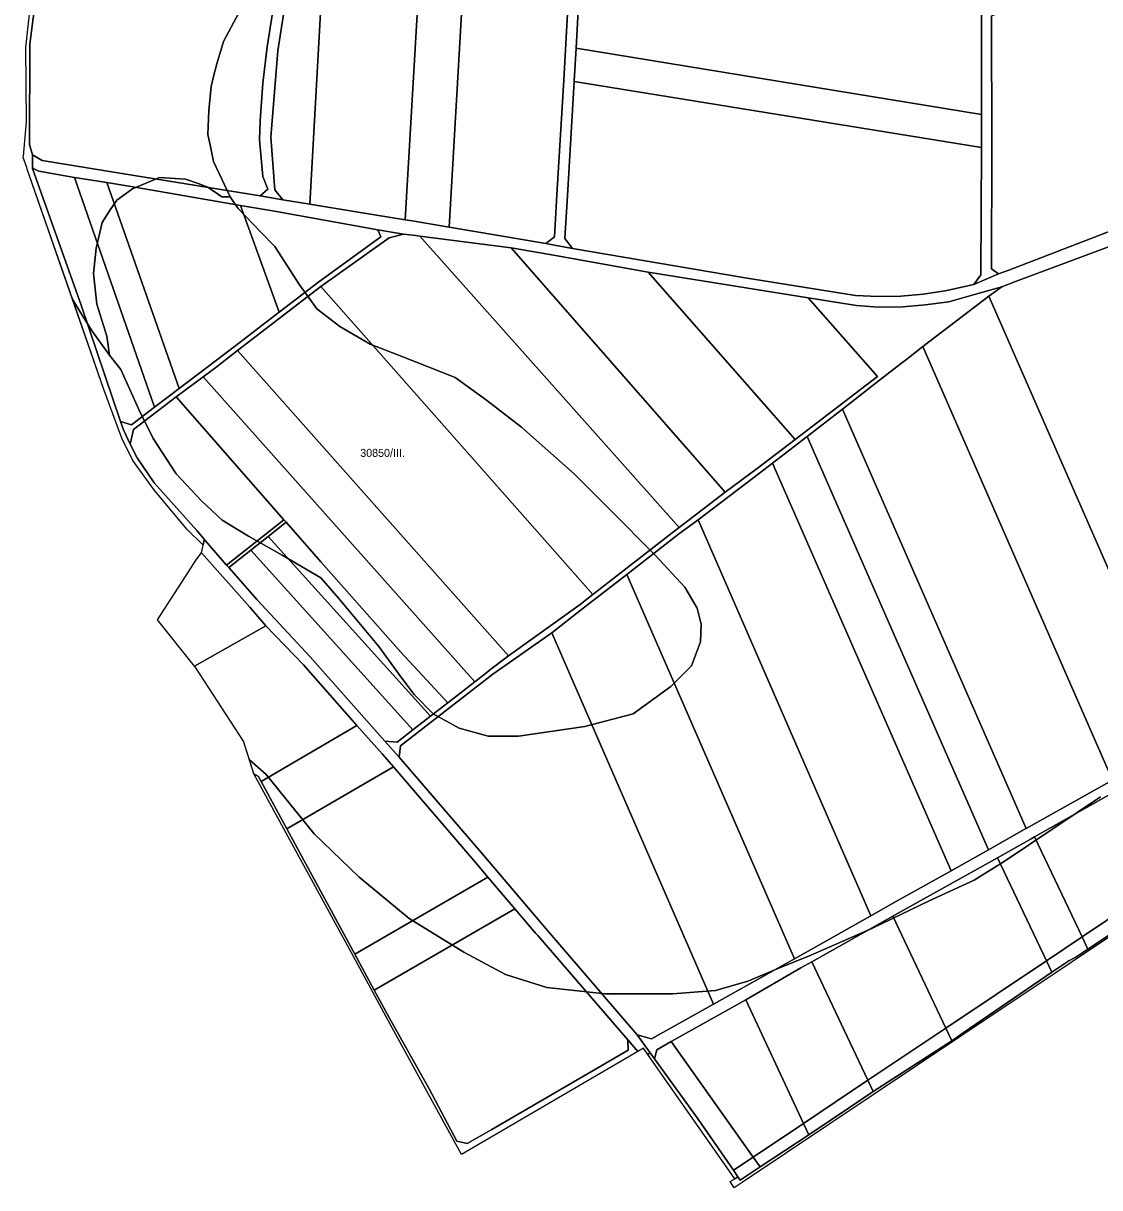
# Model space of a CAD drawing. Extents: x -541351 to -537540, y -1162694 to -1159725.
# Drawn here: x -541335 to -540662, y -1161930 to -1161203 of the extents above; entities that cross this region are included whole.
import ezdxf

# ---------------------------------------------------------------- set-up
doc = ezdxf.new("R2010")
doc.units = 0
for name, color, linetype in [('95560013', 7, 'Continuous'), ('95630013', 7, 'Continuous'), ('95640013', 7, 'Continuous'), ('95660013', 7, 'Continuous')]:
    doc.layers.add(name, color=color, linetype=linetype)

msp = doc.modelspace()

# ---------------------------------------------------------------- linework, layer by layer
at = {"layer": '95560013'}
for points in [[(-541002.5, -1161335.95), (-541008.05, -1161340.22), (-541068.49, -1161330.02), (-541054.64, -1161091.86), (-541038.24, -1161076.76), (-541018.02, -1161051.7), (-541009.77, -1161048.36), (-540991.57, -1161051.36), (-540986.52, -1161057.36), (-540989.14, -1161101.78), (-540991.75, -1161147.06), (-540996.64, -1161238.13), (-541001.01, -1161309.69)], [(-540986.52, -1161057.36), (-540991.57, -1161051.36), (-540975.41, -1161053.82), (-540979.98, -1161058.32), (-540982.72, -1161102.03), (-540985.21, -1161147.42), (-540989.12, -1161218.21), (-540990.18, -1161238.48), (-540990.23, -1161238.98), (-540994.49, -1161310.1), (-540996.06, -1161337.06), (-540991.27, -1161343.31), (-541002.57, -1161341.19), (-541008.05, -1161340.22), (-541002.5, -1161335.95), (-541001.01, -1161309.69), (-540996.64, -1161238.13), (-540991.75, -1161147.06), (-540989.14, -1161101.78)], [(-540741.17, -1161091.8), (-540735.93, -1161097.29), (-540736, -1161144.39), (-540735.68, -1161196.89), (-540735.74, -1161259.49), (-540989.12, -1161218.21), (-540985.21, -1161147.42), (-540982.72, -1161102.03), (-540979.98, -1161058.32), (-540975.41, -1161053.82), (-540941.46, -1161059.38), (-540869, -1161071.68), (-540796.53, -1161083.37)], [(-541091.62, -1161326.12), (-541095.8, -1161325.34), (-541083.35, -1161111.3), (-541073.3, -1161109.03), (-541054.64, -1161091.86), (-541068.49, -1161330.02)], [(-541145.22, -1161132.35), (-541126.35, -1161121.54), (-541083.35, -1161111.3), (-541095.8, -1161325.34), (-541125.26, -1161320.58), (-541155.46, -1161315.61)], [(-540725.06, -1161359.22), (-540729.41, -1161355.94), (-540729.28, -1161280.63), (-540729.47, -1161197.86), (-540518.17, -1161114.81), (-540508.04, -1161201.67), (-540500.7, -1161266.6), (-540504.91, -1161273.51), (-540630.42, -1161322.96), (-540718.49, -1161356.81)], [(-541170.97, -1161190.37), (-541166.19, -1161152.97), (-541161.55, -1161143.55), (-541145.22, -1161132.35), (-541155.46, -1161315.61), (-541172.43, -1161312.81), (-541177.3, -1161306.69), (-541179.83, -1161273.84), (-541175.46, -1161219.82)], [(-540990.23, -1161238.98), (-540990.18, -1161238.48), (-540989.12, -1161218.21), (-540735.74, -1161259.49), (-540735.57, -1161280.29)], [(-540800.31, -1161373.2), (-540814.5, -1161372.57), (-540883.34, -1161361.65), (-540991.27, -1161343.31), (-540996.06, -1161337.06), (-540994.49, -1161310.1), (-540990.23, -1161238.98), (-540735.57, -1161280.29), (-540735.58, -1161280.69), (-540736.07, -1161359.79), (-540740.36, -1161365.79), (-540758.33, -1161369.77), (-540772.08, -1161371.79), (-540786.11, -1161373.14)], [(-541273.81, -1161451.48), (-541298.37, -1161378.61), (-541328.81, -1161293.37), (-541328.94, -1161293), (-541328, -1161293.47), (-541324.9, -1161295), (-541302.51, -1161298.95), (-541252.67, -1161442.38), (-541267.05, -1161453.46)], [(-541252.67, -1161442.38), (-541302.51, -1161298.95), (-541282.32, -1161302.16), (-541237.22, -1161430.82)], [(-541264.86, -1161305.04), (-541198.78, -1161316.41), (-541174.69, -1161383.11), (-541202.56, -1161404.53), (-541237.22, -1161430.82), (-541282.32, -1161302.16)], [(-541198.78, -1161316.41), (-541177.67, -1161319.97), (-541113.06, -1161331.61), (-541111.07, -1161335.97), (-541149.92, -1161364.06), (-541174.69, -1161383.11)], [(-540626.04, -1161331.01), (-540602.06, -1161321.76), (-540487.95, -1161583.73), (-540514.53, -1161597.21), (-540593.57, -1161641.71), (-540609.41, -1161650.66), (-540731.05, -1161373.08), (-540722.92, -1161367.3), (-540714.45, -1161363.95)], [(-541237.22, -1161430.82), (-541202.56, -1161404.53), (-541174.69, -1161383.11), (-541149.92, -1161364.06), (-541111.07, -1161335.97), (-541113.06, -1161331.61), (-541096.97, -1161334.3), (-541105.92, -1161336.62), (-541148.7, -1161366.98), (-541200.73, -1161407.02), (-541214.31, -1161417.57), (-541222.15, -1161423.45), (-541239.06, -1161436.07), (-541265.8, -1161456.42), (-541267.7, -1161465.57), (-541271.92, -1161456.53), (-541273.81, -1161451.48), (-541267.05, -1161453.46), (-541252.67, -1161442.38)], [(-541096.97, -1161334.3), (-541090.82, -1161335.06), (-541086.82, -1161335.7), (-540924.65, -1161517.59), (-540927.06, -1161519.46), (-540978.65, -1161559.41), (-541148.7, -1161366.98), (-541105.92, -1161336.62)], [(-541086.82, -1161335.7), (-541029.57, -1161342.88), (-540895.88, -1161495.62), (-540924.65, -1161517.59)], [(-540895.88, -1161495.62), (-541029.57, -1161342.88), (-541001.92, -1161347.64), (-540944.09, -1161357.99), (-540852.18, -1161462.55), (-540875.88, -1161480.69)], [(-540944.09, -1161357.99), (-540883.03, -1161367.85), (-540843.94, -1161374.18), (-540800.7, -1161423.2), (-540852.18, -1161462.55)], [(-541148.7, -1161366.98), (-540978.65, -1161559.41), (-540986.54, -1161565.79), (-541031.23, -1161597.84), (-541200.73, -1161407.02)], [(-540852.18, -1161462.55), (-540800.7, -1161423.2), (-540843.94, -1161374.18), (-540813.72, -1161378.95), (-540800.34, -1161380.02), (-540784.84, -1161379.79), (-540770.8, -1161378.57), (-540756.03, -1161376.56), (-540740.09, -1161372.1), (-540722.92, -1161367.3), (-540731.05, -1161373.08), (-540772.43, -1161404.49), (-540782.43, -1161412.5), (-540785.62, -1161415.04), (-540799.44, -1161425.52), (-540822.56, -1161443.77), (-540844.61, -1161460.72), (-540866.29, -1161477.37), (-540874.33, -1161483.65), (-540912.8, -1161512.76), (-540925.13, -1161521.9), (-540957.39, -1161546.93), (-540985.59, -1161568.9), (-541004.21, -1161583.4), (-541041.07, -1161609.24), (-541098.89, -1161653.97), (-541099.72, -1161661.19), (-541108.6, -1161651.17), (-541100.92, -1161651.74), (-541091.05, -1161644.07), (-541080.04, -1161635.58), (-541069.2, -1161627.21), (-541052.46, -1161614.04), (-541044.94, -1161608.22), (-541043.12, -1161606.82), (-541031.23, -1161597.84), (-540986.54, -1161565.79), (-540978.65, -1161559.41), (-540927.06, -1161519.46), (-540924.65, -1161517.59), (-540895.88, -1161495.62), (-540875.88, -1161480.69)], [(-540772.43, -1161404.49), (-540731.05, -1161373.08), (-540609.41, -1161650.66), (-540636.75, -1161665.9), (-540653.69, -1161675.45)], [(-540799.44, -1161425.52), (-540785.62, -1161415.04), (-540782.43, -1161412.5), (-540772.43, -1161404.49), (-540653.69, -1161675.45), (-540664.54, -1161681.55), (-540667.99, -1161683.49), (-540707.7, -1161705.8), (-540822.56, -1161443.77)], [(-541214.31, -1161417.57), (-541200.73, -1161407.02), (-541031.23, -1161597.84), (-541043.12, -1161606.82), (-541044.94, -1161608.22), (-541052.46, -1161614.04), (-541222.15, -1161423.45)], [(-541171.76, -1161512.77), (-541239.06, -1161436.07), (-541222.15, -1161423.45), (-541052.46, -1161614.04), (-541069.2, -1161627.21), (-541098.59, -1161595.53), (-541148.61, -1161539.06), (-541170.36, -1161514.21)], [(-541267.7, -1161465.57), (-541265.8, -1161456.42), (-541239.06, -1161436.07), (-541171.76, -1161512.77), (-541207.48, -1161541.15), (-541220.9, -1161525.72), (-541221.52, -1161524.98), (-541226.07, -1161519.49), (-541252.77, -1161489.7), (-541263.44, -1161474.03)], [(-540844.61, -1161460.72), (-540822.56, -1161443.77), (-540707.7, -1161705.8), (-540708.95, -1161706.43), (-540731.37, -1161719.05)], [(-540866.29, -1161477.37), (-540844.61, -1161460.72), (-540731.37, -1161719.05), (-540754.61, -1161732.14)], [(-540874.33, -1161483.65), (-540866.29, -1161477.37), (-540754.61, -1161732.14), (-540788.4, -1161751), (-540804.81, -1161760.28), (-540912.8, -1161512.76)], [(-541207.48, -1161541.15), (-541171.76, -1161512.77), (-541170.36, -1161514.21), (-541181.49, -1161523.17), (-541192.32, -1161531.89), (-541206.21, -1161542.7)], [(-540804.81, -1161760.28), (-540852.63, -1161787.05), (-540957.39, -1161546.93), (-540925.13, -1161521.9), (-540912.8, -1161512.76)], [(-541181.49, -1161523.17), (-541170.36, -1161514.21), (-541148.61, -1161539.06), (-541098.59, -1161595.53), (-541069.2, -1161627.21), (-541080.04, -1161635.58)], [(-541181.49, -1161523.17), (-541080.04, -1161635.58), (-541091.05, -1161644.07), (-541192.32, -1161531.89)], [(-541182.97, -1161579.01), (-541227.53, -1161604.31), (-541250.72, -1161575.22), (-541242.35, -1161562.34), (-541233.17, -1161548.21), (-541226.45, -1161537.87), (-541223.3, -1161533.47), (-541193.07, -1161567.51)], [(-541188.37, -1161562.9), (-541206.21, -1161542.7), (-541192.32, -1161531.89), (-541091.05, -1161644.07), (-541100.92, -1161651.74), (-541108.6, -1161651.17), (-541155.28, -1161598.47)], [(-540903.21, -1161815.53), (-541004.21, -1161583.4), (-540985.59, -1161568.9), (-540957.39, -1161546.93), (-540852.63, -1161787.05)], [(-541190.56, -1161671.49), (-541196.86, -1161651.1), (-541226.83, -1161605.4), (-541227.53, -1161604.31), (-541182.97, -1161579.01), (-541159.44, -1161603.37), (-541126.02, -1161641.36), (-541185.97, -1161676.37), (-541187.56, -1161673.25)], [(-540903.21, -1161815.53), (-540942, -1161837.03), (-540950.97, -1161834.57), (-541008.22, -1161768), (-541047.04, -1161722.32), (-541099.72, -1161661.19), (-541098.89, -1161653.97), (-541041.07, -1161609.24), (-541004.21, -1161583.4)], [(-541110.06, -1161659.28), (-541103.29, -1161667.11), (-541169.79, -1161705.93), (-541185.97, -1161676.37), (-541126.02, -1161641.36)], [(-540950.54, -1161845.03), (-541060.78, -1161909.35), (-541106.46, -1161825.63), (-541127.01, -1161787.97), (-541190.56, -1161671.49), (-541187.56, -1161673.25), (-541185.97, -1161676.37), (-541169.79, -1161705.93), (-541146.1, -1161749.73), (-541127.42, -1161784.2), (-541115.29, -1161806.63), (-541105.77, -1161824.11), (-541080.97, -1161868.44), (-541063.54, -1161901.08), (-541057.18, -1161902.55), (-541041.8, -1161893.69), (-540956.53, -1161844.18), (-540956.77, -1161837.79)], [(-541103.29, -1161667.11), (-541051.69, -1161727.07), (-541044.31, -1161736.08), (-541127.42, -1161784.2), (-541146.1, -1161749.73), (-541169.79, -1161705.93)], [(-540672.85, -1161773.42), (-540702.46, -1161710.97), (-540654.37, -1161683.86), (-540626.51, -1161742.4)], [(-540672.85, -1161773.42), (-540695.09, -1161788.31), (-540725.63, -1161723.93), (-540704.67, -1161712.23), (-540702.46, -1161710.97)], [(-540725.63, -1161723.93), (-540695.09, -1161788.31), (-540758.04, -1161830.46), (-540791.07, -1161760.57), (-540784.37, -1161756.77)], [(-541127.42, -1161784.2), (-541044.31, -1161736.08), (-541027.44, -1161755.93), (-541115.29, -1161806.63)], [(-541063.54, -1161901.08), (-541080.97, -1161868.44), (-541105.77, -1161824.11), (-541115.29, -1161806.63), (-541027.44, -1161755.93), (-541014.23, -1161771.21), (-541012.92, -1161772.52), (-540956.77, -1161837.79), (-540956.53, -1161844.18), (-541041.8, -1161893.69), (-541057.18, -1161902.55)], [(-540758.04, -1161830.46), (-540806.69, -1161863.04), (-540841.71, -1161789.05), (-540791.07, -1161760.57)], [(-540806.69, -1161863.04), (-540846.94, -1161889.99), (-540882.97, -1161812.68), (-540848.61, -1161792.79), (-540841.71, -1161789.05)], [(-540882.97, -1161812.68), (-540846.94, -1161889.99), (-540878.37, -1161911.03), (-540929.56, -1161838.82)], [(-540929.56, -1161838.82), (-540878.37, -1161911.03), (-540890.7, -1161919.28), (-540912.77, -1161887.31), (-540940.03, -1161849.7), (-540938.7, -1161843.95)]]:
    msp.add_lwpolyline(points, close=True, dxfattribs=at)
for points in [[(-541177.48, -1161188.33), (-541182.21, -1161217.36), (-541184.87, -1161240.05), (-541186.47, -1161263.45), (-541186.85, -1161275.44), (-541184.81, -1161298.35), (-541181.75, -1161306.33), (-541186.56, -1161310.32), (-541265.26, -1161297.71), (-541322.8, -1161288.33), (-541328.76, -1161284.74), (-541330.62, -1161278.35), (-541330.42, -1161215.55), (-541323.15, -1161158.46)], [(-540654.37, -1161683.86), (-540702.46, -1161710.97), (-540704.67, -1161712.23), (-540725.63, -1161723.93), (-540784.37, -1161756.77), (-540791.07, -1161760.57), (-540841.71, -1161789.05), (-540848.61, -1161792.79), (-540882.97, -1161812.68), (-540929.56, -1161838.82), (-540938.7, -1161843.95), (-540940.03, -1161849.7), (-540942.78, -1161845.9), (-540950.97, -1161834.57), (-540942, -1161837.03), (-540903.21, -1161815.53), (-540852.63, -1161787.05), (-540804.81, -1161760.28), (-540788.4, -1161751), (-540754.61, -1161732.14), (-540731.37, -1161719.05), (-540708.95, -1161706.43), (-540707.7, -1161705.8), (-540667.99, -1161683.49), (-540664.54, -1161681.55), (-540653.69, -1161675.45)]]:
    msp.add_lwpolyline(points, dxfattribs=at)
at = {"layer": '95630013'}
msp.add_lwpolyline([(-540610.73, -1161743.43), (-540748.01, -1161835.11), (-540885.29, -1161926.8), (-540890.31, -1161930.15), (-540892.68, -1161926.19), (-540889.95, -1161924.5), (-540887.95, -1161923.26), (-540886.43, -1161925.45), (-540873.99, -1161917.2), (-540843.64, -1161897.07), (-540818.26, -1161879.98), (-540803.39, -1161870.01), (-540754.28, -1161838.41), (-540747.18, -1161833.38), (-540691.67, -1161795.5), (-540681.1, -1161788.46), (-540676.71, -1161786.07), (-540669.18, -1161781.14), (-540622.77, -1161750.26)], dxfattribs=at)
at = {"layer": '95640013'}
for points in [[(-541323.15, -1161158.46), (-541330.42, -1161215.55), (-541330.62, -1161278.35), (-541328.76, -1161284.74), (-541328.93, -1161292.34), (-541328.94, -1161293), (-541328.81, -1161293.37), (-541298.37, -1161378.61), (-541273.81, -1161451.48), (-541271.92, -1161456.53), (-541267.7, -1161465.57), (-541263.44, -1161474.03), (-541252.77, -1161489.7), (-541226.07, -1161519.49), (-541221.52, -1161524.98), (-541222.15, -1161528.65), (-541232.32, -1161518.63), (-541253.05, -1161493.9), (-541266.12, -1161475.84), (-541273, -1161461.76), (-541284.15, -1161431.35), (-541332.09, -1161293.63), (-541332.42, -1161292.68), (-541334.6, -1161286.42), (-541334.52, -1161285.55), (-541332.64, -1161264.13), (-541333.01, -1161217.8), (-541326.12, -1161154.72)], [(-541170.97, -1161190.37), (-541175.46, -1161219.82), (-541179.83, -1161273.84), (-541177.3, -1161306.69), (-541172.43, -1161312.81), (-541186.56, -1161310.32), (-541181.75, -1161306.33), (-541184.81, -1161298.35), (-541186.85, -1161275.44), (-541186.47, -1161263.45), (-541184.87, -1161240.05), (-541182.21, -1161217.36), (-541177.48, -1161188.33)], [(-540729.47, -1161197.86), (-540729.28, -1161280.63), (-540729.41, -1161355.94), (-540725.06, -1161359.22), (-540740.36, -1161365.79), (-540736.07, -1161359.79), (-540735.58, -1161280.69), (-540735.57, -1161280.29), (-540735.74, -1161259.49), (-540735.68, -1161196.89)], [(-540626.04, -1161331.01), (-540714.45, -1161363.95), (-540722.92, -1161367.3), (-540740.09, -1161372.1), (-540756.03, -1161376.56), (-540770.8, -1161378.57), (-540784.84, -1161379.79), (-540800.34, -1161380.02), (-540813.72, -1161378.95), (-540843.94, -1161374.18), (-540883.03, -1161367.85), (-540944.09, -1161357.99), (-541001.92, -1161347.64), (-541029.57, -1161342.88), (-541086.82, -1161335.7), (-541090.82, -1161335.06), (-541096.97, -1161334.3), (-541113.06, -1161331.61), (-541177.67, -1161319.97), (-541198.78, -1161316.41), (-541264.86, -1161305.04), (-541282.32, -1161302.16), (-541302.51, -1161298.95), (-541324.9, -1161295), (-541328, -1161293.47), (-541328.94, -1161293), (-541328.93, -1161292.34), (-541328.76, -1161284.74), (-541322.8, -1161288.33), (-541265.26, -1161297.71), (-541186.56, -1161310.32), (-541172.43, -1161312.81), (-541155.46, -1161315.61), (-541125.26, -1161320.58), (-541095.8, -1161325.34), (-541091.62, -1161326.12), (-541068.49, -1161330.02), (-541008.05, -1161340.22), (-541002.57, -1161341.19), (-540991.27, -1161343.31), (-540883.34, -1161361.65), (-540814.5, -1161372.57), (-540800.31, -1161373.2), (-540786.11, -1161373.14), (-540772.08, -1161371.79), (-540758.33, -1161369.77), (-540740.36, -1161365.79), (-540725.06, -1161359.22), (-540718.49, -1161356.81), (-540630.42, -1161322.96)]]:
    msp.add_lwpolyline(points, dxfattribs=at)
for points in [[(-541047.04, -1161722.32), (-541008.22, -1161768), (-540950.97, -1161834.57), (-540942.78, -1161845.9), (-540944.19, -1161846.83), (-540946.92, -1161842.92), (-540950.54, -1161845.03), (-540956.77, -1161837.79), (-541012.92, -1161772.52), (-541014.23, -1161771.21), (-541027.44, -1161755.93), (-541044.31, -1161736.08), (-541051.69, -1161727.07), (-541103.29, -1161667.11), (-541110.06, -1161659.28), (-541126.02, -1161641.36), (-541159.44, -1161603.37), (-541182.97, -1161579.01), (-541193.07, -1161567.51), (-541223.3, -1161533.47), (-541222.15, -1161528.65), (-541221.52, -1161524.98), (-541220.9, -1161525.72), (-541207.48, -1161541.15), (-541206.21, -1161542.7), (-541188.37, -1161562.9), (-541155.28, -1161598.47), (-541108.6, -1161651.17), (-541099.72, -1161661.19)], [(-540622.77, -1161750.26), (-540669.18, -1161781.14), (-540672.85, -1161773.42), (-540626.51, -1161742.4)], [(-540672.85, -1161773.42), (-540669.18, -1161781.14), (-540676.71, -1161786.07), (-540681.1, -1161788.46), (-540691.67, -1161795.5), (-540695.09, -1161788.31)], [(-540754.28, -1161838.41), (-540758.04, -1161830.46), (-540695.09, -1161788.31), (-540691.67, -1161795.5), (-540747.18, -1161833.38)], [(-540758.04, -1161830.46), (-540754.28, -1161838.41), (-540803.39, -1161870.01), (-540806.69, -1161863.04)], [(-540940.03, -1161849.7), (-540912.77, -1161887.31), (-540890.7, -1161919.28), (-540887.95, -1161923.26), (-540889.95, -1161924.5), (-540944.19, -1161846.83), (-540942.78, -1161845.9)], [(-540818.26, -1161879.98), (-540843.64, -1161897.07), (-540846.94, -1161889.99), (-540806.69, -1161863.04), (-540803.39, -1161870.01)], [(-540846.94, -1161889.99), (-540843.64, -1161897.07), (-540873.99, -1161917.2), (-540878.37, -1161911.03)], [(-540890.7, -1161919.28), (-540878.37, -1161911.03), (-540873.99, -1161917.2), (-540886.43, -1161925.45), (-540887.95, -1161923.26)]]:
    msp.add_lwpolyline(points, close=True, dxfattribs=at)
at = {"layer": '95660013'}
for points in [[(-541199.87, -1161196), (-541209.37, -1161214), (-541213.62, -1161228), (-541215.6, -1161235.78), (-541217.19, -1161242), (-541218.69, -1161257), (-541219.19, -1161272), (-541217.6, -1161279.56), (-541215.62, -1161289), (-541205.37, -1161311), (-541210.5, -1161311), (-541219.19, -1161305), (-541225.38, -1161302.78), (-541233.12, -1161300), (-541249.5, -1161299), (-541266.37, -1161306), (-541276.19, -1161313), (-541280.27, -1161319.22), (-541285.37, -1161327), (-541289.12, -1161343), (-541290.62, -1161359), (-541288.62, -1161378), (-541282.37, -1161398), (-541280.81, -1161410), (-541291.62, -1161395), (-541298.8, -1161383.26), (-541303.65, -1161375.32), (-541332.09, -1161293.63), (-541332.42, -1161292.68), (-541334.6, -1161286.42), (-541334.52, -1161285.55), (-541332.64, -1161264.13), (-541333.01, -1161217.8), (-541326.12, -1161154.72)], [(-540661.31, -1161686), (-540720.81, -1161726), (-540740.31, -1161738), (-540768.31, -1161751), (-540803.81, -1161768), (-540842.81, -1161785), (-540862.31, -1161793), (-540881.81, -1161801), (-540901.87, -1161807), (-540928.81, -1161809), (-540970.87, -1161809), (-541007.37, -1161805), (-541033.12, -1161797), (-541059.31, -1161783), (-541093.37, -1161762), (-541124.81, -1161736), (-541152.87, -1161709), (-541182.81, -1161672), (-541193.26, -1161662.74), (-541196.86, -1161651.1), (-541226.83, -1161605.4), (-541227.53, -1161604.31), (-541250.72, -1161575.22), (-541242.35, -1161562.34), (-541233.17, -1161548.21), (-541226.45, -1161537.87), (-541223.3, -1161533.47), (-541222.15, -1161528.65), (-541232.32, -1161518.63), (-541253.05, -1161493.9), (-541266.12, -1161475.84), (-541273, -1161461.76), (-541284.15, -1161431.35), (-541303.65, -1161375.32), (-541298.8, -1161383.26), (-541291.62, -1161395), (-541280.81, -1161410), (-541273.62, -1161419), (-541262.37, -1161444), (-541253.37, -1161462), (-541239, -1161484), (-541223.12, -1161501), (-541210.31, -1161513), (-541193.81, -1161523), (-541172.81, -1161535), (-541148.62, -1161549), (-541137.31, -1161562), (-541112.37, -1161592), (-541098.62, -1161611), (-541090.31, -1161622), (-541078.5, -1161634), (-541062.12, -1161643), (-541044.12, -1161648), (-541025.12, -1161648), (-540983.5, -1161642), (-540953.37, -1161634), (-540929.81, -1161617), (-540917, -1161604), (-540911.37, -1161589), (-540910.81, -1161578), (-540913.37, -1161568), (-540921.12, -1161555), (-540939.62, -1161535), (-540967.71, -1161506.67), (-540990.19, -1161484), (-541004.83, -1161471.11), (-541023.12, -1161455), (-541045.12, -1161438), (-541064.62, -1161424), (-541097.31, -1161411), (-541117.81, -1161403), (-541136.81, -1161392), (-541151.19, -1161381), (-541155.94, -1161374.33), (-541161.87, -1161366), (-541177.37, -1161342), (-541186.12, -1161333), (-541200.5, -1161318), (-541205.37, -1161311), (-541215.62, -1161289), (-541217.6, -1161279.56), (-541219.19, -1161272), (-541218.69, -1161257), (-541217.19, -1161242), (-541215.6, -1161235.78), (-541213.62, -1161228), (-541209.37, -1161214), (-541199.87, -1161196)], [(-540610.73, -1161743.43), (-540748.01, -1161835.11), (-540885.29, -1161926.8), (-540890.31, -1161930.15), (-540892.68, -1161926.19), (-540889.95, -1161924.5), (-540944.19, -1161846.83), (-540946.92, -1161842.92), (-540950.54, -1161845.03), (-541060.78, -1161909.35), (-541106.46, -1161825.63), (-541127.01, -1161787.97), (-541190.56, -1161671.49), (-541193.26, -1161662.74), (-541182.81, -1161672), (-541152.87, -1161709), (-541124.81, -1161736), (-541093.37, -1161762), (-541059.31, -1161783), (-541033.12, -1161797), (-541007.37, -1161805), (-540970.87, -1161809), (-540928.81, -1161809), (-540901.87, -1161807), (-540881.81, -1161801), (-540862.31, -1161793), (-540842.81, -1161785), (-540803.81, -1161768), (-540768.31, -1161751), (-540740.31, -1161738), (-540720.81, -1161726), (-540661.31, -1161686)]]:
    msp.add_lwpolyline(points, dxfattribs=at)
msp.add_lwpolyline([(-541205.37, -1161311), (-541200.5, -1161318), (-541186.12, -1161333), (-541177.37, -1161342), (-541161.87, -1161366), (-541155.94, -1161374.33), (-541151.19, -1161381), (-541136.81, -1161392), (-541117.81, -1161403), (-541097.31, -1161411), (-541064.62, -1161424), (-541045.12, -1161438), (-541023.12, -1161455), (-541004.83, -1161471.11), (-540990.19, -1161484), (-540967.71, -1161506.67), (-540939.62, -1161535), (-540921.12, -1161555), (-540913.37, -1161568), (-540910.81, -1161578), (-540911.37, -1161589), (-540917, -1161604), (-540929.81, -1161617), (-540953.37, -1161634), (-540983.5, -1161642), (-541025.12, -1161648), (-541044.12, -1161648), (-541062.12, -1161643), (-541078.5, -1161634), (-541090.31, -1161622), (-541098.62, -1161611), (-541112.37, -1161592), (-541137.31, -1161562), (-541148.62, -1161549), (-541172.81, -1161535), (-541193.81, -1161523), (-541210.31, -1161513), (-541223.12, -1161501), (-541239, -1161484), (-541253.37, -1161462), (-541262.37, -1161444), (-541273.62, -1161419), (-541280.81, -1161410), (-541282.37, -1161398), (-541288.62, -1161378), (-541290.62, -1161359), (-541289.12, -1161343), (-541285.37, -1161327), (-541280.27, -1161319.22), (-541276.19, -1161313), (-541266.37, -1161306), (-541249.5, -1161299), (-541233.12, -1161300), (-541225.38, -1161302.78), (-541219.19, -1161305), (-541210.5, -1161311)], close=True, dxfattribs=at)

# ---------------------------------------------------------------- texts
msp.add_text('30850/III.', height=5, rotation=360, dxfattribs=at).set_placement((-541123.99, -1161473.5))

doc.saveas('drawing.dxf')
